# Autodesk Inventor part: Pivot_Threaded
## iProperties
Shininess: 0.0
Length Units: 11272
Angle Units: 11279
Time Units: 11290
Mass Units: 11283
Length Display Precision: 2
Angle Display Precision: 1
Created: 1999-05
Part Number: Pivot_Threaded
Document SubType Name: Modeling
Designer: Administrator
Density: 1 g/cm^3
Density: 0.0
Volumn: 0.0
Area: 0.0
PropertySet Name: Model Information
Control State: 0
Master: False
Checked Out: False
Author: Administrator
